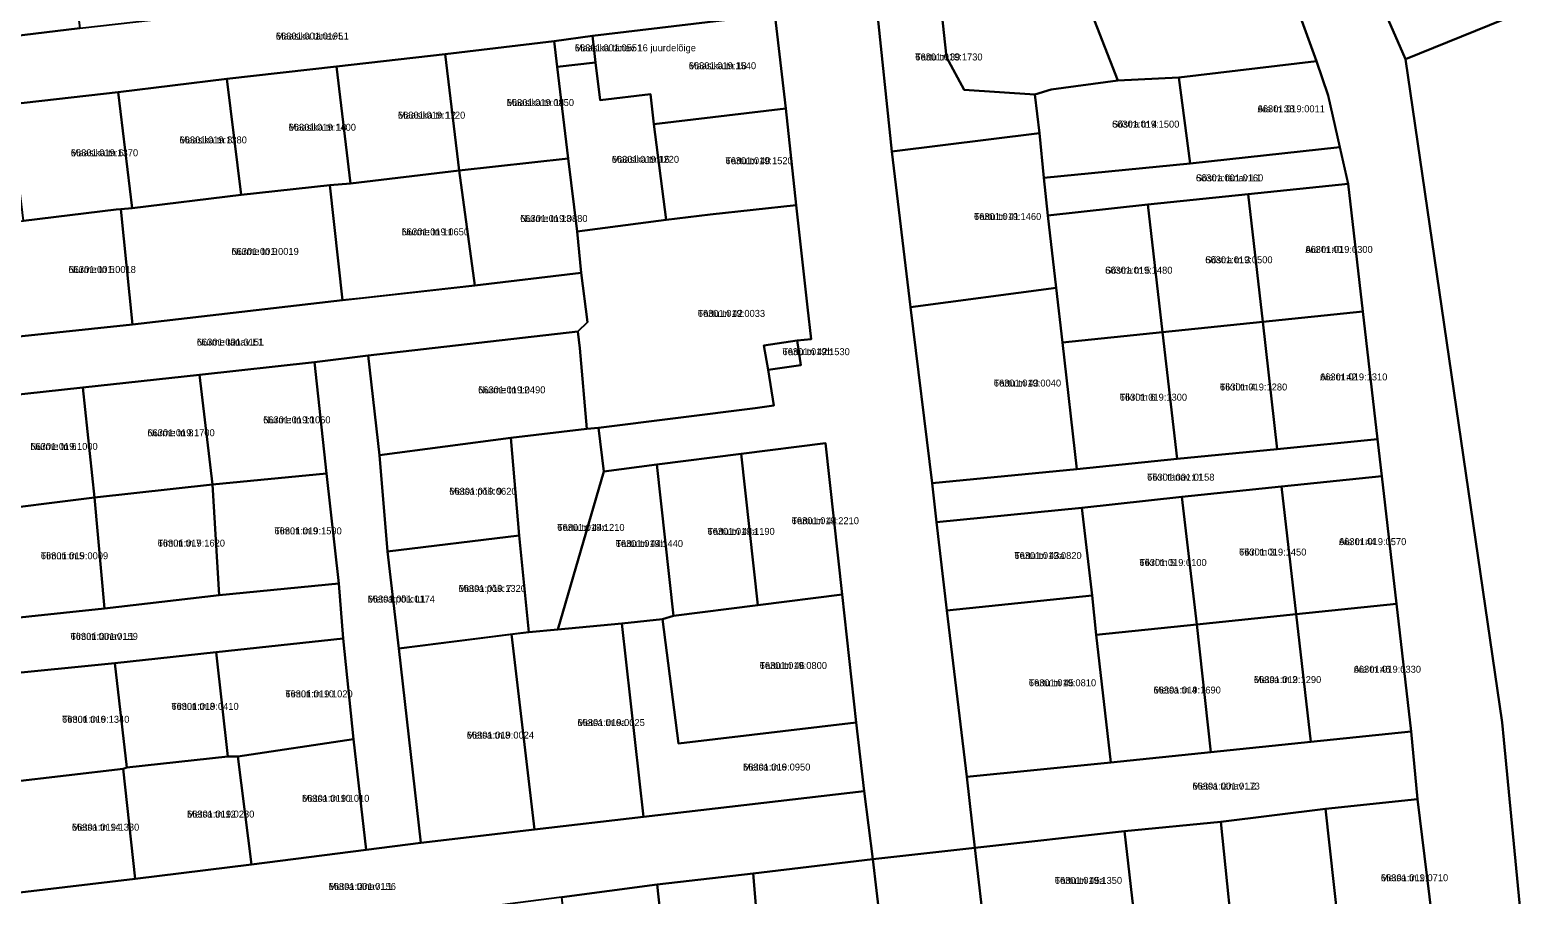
# Model space of a CAD drawing. Extents: x 632278 to 636344, y 6578401 to 6583362.
# Drawn here: x 634323.6 to 634648.4, y 6579215.9 to 6579402.2 of the extents above; entities that cross this region are included whole.
import ezdxf

# ---------------------------------------------------------------- set-up
doc = ezdxf.new("R2010")
doc.units = 0
for name, color, linetype in [('L_AADRESS', 7, 'Continuous'), ('PIIR', 7, 'Continuous'), ('TUNNUS', 7, 'Continuous')]:
    doc.layers.add(name, color=color, linetype=linetype)

msp = doc.modelspace()

# ---------------------------------------------------------------- linework, layer by layer
at = {"layer": 'PIIR'}
for points in [[(634683.61, 6578861.97), (634681.47, 6578962.07), (634668.96, 6578959.68), (634659.72, 6579055.77), (634657.39, 6579079.77), (634640.69, 6579253.02), (634619.84, 6579395.9), (634646.99, 6579406.93), (634634.13, 6579438.99), (634626.39, 6579457.25), (634762.59, 6579522.66), (634923.65, 6579631.25), (634921.5, 6579637.56), (634910.69, 6579669.18), (634900.72, 6579698.39), (634889.72, 6579730.89), (634877.71, 6579767.04), (634867.15, 6579797.74), (634863.84, 6579807.62), (634853.17, 6579839.67), (634843.13, 6579869.84), (634827.14, 6579901.97), (634840.49, 6579911.35)], [(634606.07, 6579427.5), (634619.84, 6579395.9), (634640.69, 6579253.02), (634657.39, 6579079.77), (634642.31, 6579072.08), (634637.99, 6579108.05), (634634.64, 6579135.86), (634631.42, 6579162.67), (634629.92, 6579170.43), (634626.53, 6579203.23), (634622.48, 6579236.56), (634621.08, 6579251.12), (634617.91, 6579278.62), (634614.75, 6579306.11), (634613.83, 6579314.07), (634610.67, 6579341.56), (634607.5, 6579369.06), (634605.71, 6579376.95), (634603.2, 6579388.09), (634600.67, 6579395.5), (634584.49, 6579440.21)], [(634505.81, 6579408.32), (634509.22, 6579376.05), (634513.25, 6579342.54), (634517.89, 6579304.62), (634518.82, 6579296.19), (634521.08, 6579277.2), (634525.36, 6579241.37), (634527.1, 6579226.08), (634505.1, 6579223.6), (634503.27, 6579238.27), (634501.54, 6579253.04), (634498.49, 6579280.62), (634494.93, 6579313.2), (634476.74, 6579310.92), (634458.59, 6579308.6), (634447.13, 6579307.14), (634446, 6579316.49), (634479.76, 6579320.78), (634483.76, 6579321.32), (634482.56, 6579329.02), (634489.6, 6579330.03), (634488.81, 6579335.32), (634491.81, 6579335.62), (634491.04, 6579342.52), (634488.57, 6579364.51), (634486.34, 6579385.27), (634483.98, 6579405.6)], [(634509.88, 6579183.14), (634505.1, 6579223.6), (634527.1, 6579226.08), (634529.28, 6579206.94)]]:
    msp.add_lwpolyline(points, dxfattribs=at)
for points in [[(634308.98, 6579427.03), (634305.89, 6579441.9), (634302.48, 6579459.52), (634322.77, 6579465.57), (634327.7, 6579453.46), (634330.36, 6579432.33), (634334.25, 6579402.61), (634312.32, 6579399.96)], [(634557.88, 6579391.35), (634545.07, 6579424.38), (634584.49, 6579440.21), (634600.67, 6579395.5), (634571.03, 6579392)], [(634619.84, 6579395.9), (634606.07, 6579427.5), (634634.13, 6579438.99), (634646.99, 6579406.93)], [(634545.07, 6579424.38), (634557.88, 6579391.35), (634543.51, 6579389.39), (634540.01, 6579388.31), (634524.76, 6579389.33), (634520.96, 6579396.37), (634519.91, 6579406.31), (634525.47, 6579408.59), (634522.75, 6579415.25)], [(634268.81, 6579394.42), (634290.67, 6579396.85), (634312.32, 6579399.96), (634334.25, 6579402.61), (634353.96, 6579404.84), (634386.38, 6579408.93), (634410.31, 6579411.81), (634434.41, 6579414.49), (634455.62, 6579416.97), (634478.47, 6579419.65), (634483.98, 6579405.6), (634444.7, 6579400.97), (634436.45, 6579399.81), (634413, 6579397.02), (634389.59, 6579394.37), (634365.9, 6579391.72), (634342.49, 6579388.84), (634319.1, 6579386.17), (634295.86, 6579383.41), (634269.57, 6579380.68)], [(634505.81, 6579408.32), (634522.75, 6579415.25), (634525.47, 6579408.59), (634519.91, 6579406.31), (634520.96, 6579396.37), (634524.76, 6579389.33), (634540.01, 6579388.31), (634541, 6579379.96), (634509.22, 6579376.05)], [(634457.21, 6579388.4), (634446.36, 6579387.12), (634445.39, 6579395.24), (634444.7, 6579400.97), (634483.98, 6579405.6), (634486.34, 6579385.27), (634457.96, 6579381.94)], [(634445.39, 6579395.24), (634437.11, 6579394.27), (634436.45, 6579399.81), (634444.7, 6579400.97)], [(634413, 6579397.02), (634436.45, 6579399.81), (634437.11, 6579394.27), (634439.45, 6579374.5), (634416, 6579371.96)], [(634365.9, 6579391.72), (634389.59, 6579394.37), (634392.61, 6579369.14), (634388.12, 6579368.77), (634369.01, 6579366.71)], [(634389.59, 6579394.37), (634413, 6579397.02), (634416, 6579371.96), (634392.61, 6579369.14)], [(634439.45, 6579374.5), (634437.11, 6579394.27), (634445.39, 6579395.24), (634446.36, 6579387.12), (634457.21, 6579388.4), (634457.96, 6579381.94), (634460.6, 6579361.35), (634441.4, 6579358.79)], [(634603.2, 6579388.09), (634605.71, 6579376.95), (634573.46, 6579373.48), (634571.03, 6579392), (634600.67, 6579395.5)], [(634342.49, 6579388.84), (634365.9, 6579391.72), (634369.01, 6579366.71), (634345.55, 6579363.83)], [(634541, 6579379.96), (634540.01, 6579388.31), (634543.51, 6579389.39), (634557.88, 6579391.35), (634571.03, 6579392), (634573.46, 6579373.48), (634541.98, 6579370.38)], [(634319.1, 6579386.17), (634342.49, 6579388.84), (634345.55, 6579363.83), (634343.1, 6579363.62), (634342.09, 6579363.53), (634322.11, 6579361.14)], [(634470.1, 6579362.49), (634460.6, 6579361.35), (634457.96, 6579381.94), (634486.34, 6579385.27), (634488.57, 6579364.51)], [(634509.22, 6579376.05), (634541, 6579379.96), (634541.98, 6579370.38), (634542.79, 6579362.27), (634544.58, 6579346.7), (634513.25, 6579342.54)], [(634416, 6579371.96), (634439.45, 6579374.5), (634441.4, 6579358.79), (634442.27, 6579349.92), (634419.39, 6579347.18)], [(634541.98, 6579370.38), (634573.46, 6579373.48), (634605.71, 6579376.95), (634607.5, 6579369.06), (634585.94, 6579366.83), (634564.36, 6579364.6), (634542.79, 6579362.27)], [(634390.83, 6579344), (634388.12, 6579368.77), (634392.61, 6579369.14), (634416, 6579371.96), (634419.39, 6579347.18), (634395.19, 6579344.43)], [(634345.61, 6579338.76), (634343.1, 6579363.62), (634345.55, 6579363.83), (634369.01, 6579366.71), (634388.12, 6579368.77), (634390.83, 6579344)], [(634610.67, 6579341.56), (634589.1, 6579339.34), (634585.94, 6579366.83), (634607.5, 6579369.06)], [(634564.36, 6579364.6), (634585.94, 6579366.83), (634589.1, 6579339.34), (634567.52, 6579337.11)], [(634320.46, 6579336.13), (634318.16, 6579360.78), (634322.11, 6579361.14), (634342.09, 6579363.53), (634343.1, 6579363.62), (634345.61, 6579338.76)], [(634441.4, 6579358.79), (634460.6, 6579361.35), (634470.1, 6579362.49), (634488.57, 6579364.51), (634491.04, 6579342.52), (634491.81, 6579335.62), (634488.81, 6579335.32), (634481.64, 6579334.26), (634482.56, 6579329.02), (634483.76, 6579321.32), (634479.76, 6579320.78), (634446, 6579316.49), (634443.49, 6579316.33), (634441.99, 6579333.65), (634441.55, 6579337.28), (634443.67, 6579339.3), (634442.27, 6579349.92)], [(634544.58, 6579346.7), (634542.79, 6579362.27), (634564.36, 6579364.6), (634567.52, 6579337.11), (634545.95, 6579334.88)], [(634272.09, 6579330.6), (634296.63, 6579333.4), (634320.46, 6579336.13), (634345.61, 6579338.76), (634390.83, 6579344), (634419.39, 6579347.18), (634442.27, 6579349.92), (634443.67, 6579339.3), (634441.55, 6579337.28), (634396.36, 6579332.11), (634384.81, 6579330.68), (634360.06, 6579327.91), (634334.91, 6579325.18), (634309.88, 6579322.45), (634272.43, 6579318.56)], [(634544.58, 6579346.7), (634545.95, 6579334.88), (634549.09, 6579307.64), (634517.89, 6579304.62), (634513.25, 6579342.54)], [(634567.52, 6579337.11), (634589.1, 6579339.34), (634592.25, 6579311.94), (634570.67, 6579309.82)], [(634589.1, 6579339.34), (634610.67, 6579341.56), (634613.83, 6579314.07), (634592.25, 6579311.94)], [(634441.55, 6579337.28), (634441.99, 6579333.65), (634443.49, 6579316.33), (634427.11, 6579314.34), (634398.84, 6579310.62), (634396.36, 6579332.11)], [(634545.95, 6579334.88), (634567.52, 6579337.11), (634570.67, 6579309.82), (634549.09, 6579307.64)], [(634488.81, 6579335.32), (634489.6, 6579330.03), (634482.56, 6579329.02), (634481.64, 6579334.26)], [(634384.81, 6579330.68), (634387.44, 6579306.66), (634362.84, 6579304.31), (634360.06, 6579327.91)], [(634384.81, 6579330.68), (634396.36, 6579332.11), (634398.84, 6579310.62), (634400.55, 6579289.85), (634403.02, 6579269.01), (634407.74, 6579227.15), (634395.93, 6579225.64), (634393.25, 6579249.45), (634391.01, 6579271.16), (634390.03, 6579282.97), (634387.44, 6579306.66)], [(634334.91, 6579325.18), (634360.06, 6579327.91), (634362.84, 6579304.31), (634337.44, 6579301.52)], [(634309.88, 6579322.45), (634334.91, 6579325.18), (634337.44, 6579301.52), (634312.11, 6579298.34)], [(634431.02, 6579272.53), (634428.95, 6579293.35), (634427.11, 6579314.34), (634443.49, 6579316.33), (634446, 6579316.49), (634447.13, 6579307.14), (634437.24, 6579273.09)], [(634398.84, 6579310.62), (634427.11, 6579314.34), (634428.95, 6579293.35), (634400.55, 6579289.85)], [(634476.74, 6579310.92), (634494.93, 6579313.2), (634498.49, 6579280.62), (634480.34, 6579278.31)], [(634517.89, 6579304.62), (634549.09, 6579307.64), (634570.67, 6579309.82), (634592.25, 6579311.94), (634613.83, 6579314.07), (634614.75, 6579306.11), (634593.18, 6579303.88), (634571.69, 6579301.62), (634550.15, 6579299.31), (634518.82, 6579296.19)], [(634458.59, 6579308.6), (634476.74, 6579310.92), (634480.34, 6579278.31), (634462.18, 6579276.01)], [(634362.84, 6579304.31), (634387.44, 6579306.66), (634390.03, 6579282.97), (634364.31, 6579280.48)], [(634437.24, 6579273.09), (634447.13, 6579307.14), (634458.59, 6579308.6), (634462.18, 6579276.01), (634459.82, 6579275.3), (634451.02, 6579274.34)], [(634337.44, 6579301.52), (634362.84, 6579304.31), (634364.31, 6579280.48), (634339.59, 6579277.58)], [(634571.69, 6579301.62), (634593.18, 6579303.88), (634596.34, 6579276.39), (634574.93, 6579274.14)], [(634614.75, 6579306.11), (634617.91, 6579278.62), (634596.34, 6579276.39), (634593.18, 6579303.88)], [(634312.11, 6579298.34), (634337.44, 6579301.52), (634339.59, 6579277.58), (634314.38, 6579274.91)], [(634571.69, 6579301.62), (634574.93, 6579274.14), (634553.26, 6579271.93), (634552.35, 6579280.41), (634550.15, 6579299.31)], [(634518.82, 6579296.19), (634550.15, 6579299.31), (634552.35, 6579280.41), (634521.08, 6579277.2)], [(634400.55, 6579289.85), (634428.95, 6579293.35), (634431.02, 6579272.53), (634403.02, 6579269.01)], [(634274.73, 6579270.67), (634314.38, 6579274.91), (634339.59, 6579277.58), (634364.31, 6579280.48), (634390.03, 6579282.97), (634391.01, 6579271.16), (634363.66, 6579268.22), (634341.77, 6579265.8), (634316.49, 6579263.32), (634275.24, 6579258.73)], [(634459.82, 6579275.3), (634462.18, 6579276.01), (634480.34, 6579278.31), (634498.49, 6579280.62), (634501.54, 6579253.04), (634463.25, 6579248.51)], [(634521.08, 6579277.2), (634552.35, 6579280.41), (634553.26, 6579271.93), (634556.36, 6579244.43), (634525.36, 6579241.37)], [(634596.34, 6579276.39), (634617.91, 6579278.62), (634621.08, 6579251.12), (634599.51, 6579248.89)], [(634427.28, 6579272.06), (634431.02, 6579272.53), (634437.24, 6579273.09), (634451.02, 6579274.34), (634455.69, 6579232.75), (634432.23, 6579230.01)], [(634451.02, 6579274.34), (634459.82, 6579275.3), (634463.25, 6579248.51), (634501.54, 6579253.04), (634503.27, 6579238.27), (634455.69, 6579232.75)], [(634553.26, 6579271.93), (634574.93, 6579274.14), (634577.93, 6579246.66), (634556.36, 6579244.43)], [(634574.93, 6579274.14), (634596.34, 6579276.39), (634599.51, 6579248.89), (634577.93, 6579246.66)], [(634366.18, 6579245.75), (634363.66, 6579268.22), (634391.01, 6579271.16), (634393.25, 6579249.45), (634368.27, 6579245.75)], [(634403.02, 6579269.01), (634427.28, 6579272.06), (634432.23, 6579230.01), (634407.74, 6579227.15)], [(634341.77, 6579265.8), (634363.66, 6579268.22), (634366.18, 6579245.75), (634344.36, 6579243.32)], [(634316.49, 6579263.32), (634341.77, 6579265.8), (634344.36, 6579243.32), (634343.62, 6579243.06), (634319.06, 6579240.16)], [(634556.36, 6579244.43), (634577.93, 6579246.66), (634599.51, 6579248.89), (634621.08, 6579251.12), (634622.48, 6579236.56), (634602.6, 6579234.42), (634580.11, 6579231.66), (634559.3, 6579229.61), (634527.1, 6579226.08), (634525.36, 6579241.37)], [(634368.27, 6579245.75), (634393.25, 6579249.45), (634395.93, 6579225.64), (634371.24, 6579222.48)], [(634344.36, 6579243.32), (634366.18, 6579245.75), (634368.27, 6579245.75), (634371.24, 6579222.48), (634346.19, 6579219.38), (634343.62, 6579243.06)], [(634319.06, 6579240.16), (634343.62, 6579243.06), (634346.19, 6579219.38), (634321.33, 6579216.45)], [(634278.15, 6579211.22), (634321.33, 6579216.45), (634346.19, 6579219.38), (634371.24, 6579222.48), (634395.93, 6579225.64), (634407.74, 6579227.15), (634432.23, 6579230.01), (634455.69, 6579232.75), (634503.27, 6579238.27), (634505.1, 6579223.6), (634479.32, 6579220.54), (634458.68, 6579218.14), (634438.08, 6579215.39), (634426.4, 6579213.93), (634394.54, 6579209.62), (634362.56, 6579205.91), (634351.12, 6579204.36), (634319.85, 6579200.59), (634279.04, 6579195.68)], [(634602.6, 6579234.42), (634622.48, 6579236.56), (634626.53, 6579203.23), (634606.27, 6579201.17)], [(634561.49, 6579210.83), (634559.3, 6579229.61), (634580.11, 6579231.66), (634583.48, 6579198.62), (634585.04, 6579187.19), (634575.35, 6579185.93), (634575.47, 6579184.08), (634564.78, 6579182.65)], [(634602.6, 6579234.42), (634606.27, 6579201.17), (634607.51, 6579189.63), (634585.04, 6579187.19), (634583.48, 6579198.62), (634580.11, 6579231.66)], [(634527.1, 6579226.08), (634559.3, 6579229.61), (634561.49, 6579210.83), (634529.28, 6579206.94)], [(634461.81, 6579188.97), (634481.8, 6579191.32), (634479.32, 6579220.54), (634505.1, 6579223.6), (634509.88, 6579183.14), (634462.69, 6579177.91)], [(634479.32, 6579220.54), (634481.8, 6579191.32), (634461.81, 6579188.97), (634458.68, 6579218.14)], [(634438.08, 6579215.39), (634458.68, 6579218.14), (634461.81, 6579188.97), (634441.36, 6579185.69)]]:
    msp.add_lwpolyline(points, close=True, dxfattribs=at)

# ---------------------------------------------------------------- texts
at = {"layer": 'L_AADRESS'}
for s, p in [('Maasika tänav L1', (634376.5, 6579400.16)), ('Maasika tänav 16 juurdelõige', (634440.91, 6579397.62)), ('Tartu tn 39', (634514.25, 6579395.65)), ('Maasika tn 18', (634465.46, 6579393.77)), ('Maasika tn 12', (634402.8, 6579383.12)), ('Maasika tn 14', (634426.23, 6579385.83)), ('Aia tn 38', (634588.01, 6579384.49)), ('Maasika tn 10', (634379.25, 6579380.51)), ('Sõstra tn 4', (634556.65, 6579381.19)), ('Maasika tn 8', (634355.75, 6579377.78)), ('Maasika tn 6', (634332.32, 6579375.02)), ('Maasika tn 16', (634448.86, 6579373.6)), ('Tartu tn 40', (634473.35, 6579373.31)), ('Sõstra tänav L1', (634574.72, 6579369.61)), ('Nurme tn 13', (634429.14, 6579360.86)), ('Tartu tn 41', (634526.9, 6579361.29)), ('Nurme tn 11', (634403.61, 6579357.98)), ('Nurme tn 9', (634366.93, 6579353.77)), ('Aia tn 40', (634598.3, 6579354.2)), ('Sõstra tn 3', (634576.73, 6579351.97)), ('Nurme tn 5', (634331.83, 6579349.88)), ('Sõstra tn 5', (634555.16, 6579349.72)), ('Tartu tn 42', (634467.4, 6579340.42)), ('Nurme tänav L1', (634359.47, 6579334.24)), ('Tartu tn 42b', (634485.64, 6579332.17)), ('Tartu tn 43', (634531.17, 6579325.41)), ('Tikri tn 4', (634579.89, 6579324.56)), ('Aia tn 42', (634601.46, 6579326.73)), ('Nurme tn 12', (634420.07, 6579323.95)), ('Tikri tn 6', (634558.31, 6579322.36)), ('Nurme tn 8', (634348.82, 6579314.71)), ('Nurme tn 10', (634373.77, 6579317.49)), ('Nurme tn 6', (634323.61, 6579311.76)), ('Tikri tänav L1', (634564.21, 6579305.13)), ('Metsa põik 9', (634413.86, 6579302.1)), ('Tartu tn 44', (634487.62, 6579295.76)), ('Timuti tn 9', (634376.19, 6579293.57)), ('Tartu tn 44c', (634437.12, 6579294.32)), ('Tartu tn 44a', (634469.47, 6579293.46)), ('Timuti tn 7', (634351.03, 6579290.94)), ('Tartu tn 44b', (634449.71, 6579290.84)), ('Tikri tn 3', (634584.02, 6579289.01)), ('Aia tn 44', (634605.54, 6579291.25)), ('Timuti tn 5', (634325.86, 6579288.21)), ('Tartu tn 43a', (634535.6, 6579288.25)), ('Tikri tn 5', (634562.54, 6579286.76)), ('Metsa põik L1', (634396.28, 6579278.89)), ('Metsa põik 7', (634415.87, 6579281.18)), ('Timuti tänav L1', (634332.27, 6579270.85)), ('Tartu tn 46', (634480.73, 6579264.57)), ('Aia tn 46', (634608.71, 6579263.76)), ('Tartu tn 45', (634538.72, 6579260.85)), ('Metsa tn 4', (634565.59, 6579259.29)), ('Metsa tn 2', (634587.22, 6579261.53)), ('Timuti tn 10', (634378.54, 6579258.46)), ('Timuti tn 6', (634330.44, 6579252.98)), ('Timuti tn 8', (634353.98, 6579255.77)), ('Metsa tn 8', (634417.62, 6579249.58)), ('Metsa tn 6a', (634441.48, 6579252.28)), ('Metsa tn 6', (634477.15, 6579242.7)), ('Metsa tänav L2', (634573.98, 6579238.6)), ('Metsa tn 10', (634382.14, 6579235.96)), ('Metsa tn 12', (634357.36, 6579232.57)), ('Metsa tn 14', (634332.56, 6579229.75)), ('Tartu tn 45a', (634544.31, 6579218.28)), ('Metsa tn 1', (634614.57, 6579218.86)), ('Metsa tänav L1', (634387.87, 6579216.98))]:
    msp.add_text(s, height=1.5, dxfattribs=at).set_placement(p)
at = {"layer": 'TUNNUS'}
for s, p in [('66301:001:0195', (634376.5, 6579400.16)), ('66301:001:0551', (634440.91, 6579397.62)), ('66301:019:1730', (634514.25, 6579395.65)), ('66301:019:1540', (634465.46, 6579393.77)), ('66301:019:1720', (634402.8, 6579383.12)), ('66301:019:0850', (634426.23, 6579385.83)), ('66301:019:0011', (634588.01, 6579384.49)), ('66301:019:1400', (634379.25, 6579380.51)), ('66301:019:1500', (634556.65, 6579381.19)), ('66301:019:1380', (634355.75, 6579377.78)), ('66301:019:1370', (634332.32, 6579375.02)), ('66301:019:1220', (634448.86, 6579373.6)), ('66301:019:1520', (634473.35, 6579373.31)), ('66301:001:0160', (634574.72, 6579369.61)), ('66301:019:0880', (634429.14, 6579360.86)), ('66301:019:1460', (634526.9, 6579361.29)), ('66301:019:0650', (634403.61, 6579357.98)), ('66301:001:0019', (634366.93, 6579353.77)), ('66301:019:0300', (634598.3, 6579354.2)), ('66301:019:0500', (634576.73, 6579351.97)), ('66301:001:0018', (634331.83, 6579349.88)), ('66301:019:1480', (634555.16, 6579349.72)), ('66301:019:0033', (634467.4, 6579340.42)), ('66301:001:0151', (634359.47, 6579334.24)), ('66301:019:1530', (634485.64, 6579332.17)), ('66301:019:0040', (634531.17, 6579325.41)), ('66301:019:1280', (634579.89, 6579324.56)), ('66301:019:1310', (634601.46, 6579326.73)), ('66301:019:0490', (634420.07, 6579323.95)), ('66301:019:1300', (634558.31, 6579322.36)), ('66301:019:1700', (634348.82, 6579314.71)), ('66301:019:1060', (634373.77, 6579317.49)), ('66301:019:1000', (634323.61, 6579311.76)), ('66301:001:0158', (634564.21, 6579305.13)), ('66301:019:0620', (634413.86, 6579302.1)), ('66301:019:2210', (634487.62, 6579295.76)), ('66301:019:1590', (634376.19, 6579293.57)), ('66301:019:1210', (634437.12, 6579294.32)), ('66301:019:1190', (634469.47, 6579293.46)), ('66301:019:1620', (634351.03, 6579290.94)), ('66301:019:1440', (634449.71, 6579290.84)), ('66301:019:1450', (634584.02, 6579289.01)), ('66301:019:0570', (634605.54, 6579291.25)), ('66301:019:0009', (634325.86, 6579288.21)), ('66301:019:0820', (634535.6, 6579288.25)), ('66301:019:0100', (634562.54, 6579286.76)), ('66301:001:0174', (634396.28, 6579278.89)), ('66301:019:1320', (634415.87, 6579281.18)), ('66301:001:0159', (634332.27, 6579270.85)), ('66301:019:0800', (634480.73, 6579264.57)), ('66301:019:0330', (634608.71, 6579263.76)), ('66301:019:0810', (634538.72, 6579260.85)), ('66301:019:1690', (634565.59, 6579259.29)), ('66301:019:1290', (634587.22, 6579261.53)), ('66301:019:1020', (634378.54, 6579258.46)), ('66301:019:1340', (634330.44, 6579252.98)), ('66301:019:0410', (634353.98, 6579255.77)), ('66301:019:0024', (634417.62, 6579249.58)), ('66301:019:0025', (634441.48, 6579252.28)), ('66301:019:0950', (634477.15, 6579242.7)), ('66301:001:0173', (634573.98, 6579238.6)), ('66301:019:1010', (634382.14, 6579235.96)), ('66301:019:0230', (634357.36, 6579232.57)), ('66301:019:1330', (634332.56, 6579229.75)), ('66301:019:1350', (634544.31, 6579218.28)), ('66301:019:0710', (634614.57, 6579218.86)), ('66301:001:0156', (634387.87, 6579216.98))]:
    msp.add_text(s, height=1.5, dxfattribs=at).set_placement(p)

doc.saveas('drawing.dxf')
